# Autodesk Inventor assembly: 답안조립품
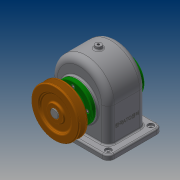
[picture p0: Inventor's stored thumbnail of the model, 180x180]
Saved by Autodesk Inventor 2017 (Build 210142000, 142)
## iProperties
Part Number: 답안조립품
Material: 일반
Document SubType Name: Assembly
Designer: 20
Author: 20
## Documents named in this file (14)
- C:\Users\20\Desktop\480310V1004\답안조립품.iam
- C:\Users\20\Desktop\480310V1004\본체.ipt
- C:\Users\20\Desktop\480310V1004\앞커버.ipt
- C:\Users\20\Desktop\480310V1004\뒤커버.ipt
- C:\Users\20\Desktop\480310V1004\베어링 6203.ipt
- C:\Users\20\Desktop\480310V1004\오일 실 28 40 8.ipt
- C:\Users\20\Desktop\480310V1004\축.ipt
- C:\Users\20\Desktop\480310V1004\키 6x6x22.ipt
- C:\Users\20\Desktop\480310V1004\스퍼기어.ipt
- C:\Users\20\Desktop\480310V1004\키 5x5x18.ipt
- C:\Users\20\Desktop\480310V1004\부시.ipt
- C:\Users\20\Desktop\480310V1004\V-벨트풀리.ipt
- C:\Users\20\Desktop\480310V1004\멈춤나사 M4.ipt
- C:\Users\20\Desktop\480310V1004\볼트 M4.ipt
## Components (1 placed, 1 different names)
1. V-벨트풀리:1 — 플러쉬:2
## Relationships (1: Flush 1)
- 플러쉬:2 [Flush]: V-벨트풀리:1
